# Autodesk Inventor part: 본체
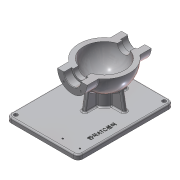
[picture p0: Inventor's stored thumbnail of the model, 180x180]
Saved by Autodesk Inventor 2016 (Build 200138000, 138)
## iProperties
Created: 2015-12
Part Number: 본체
Material: 알루미늄 6061
Document SubType Name: Modeling
Designer: mduedu
Density: 2.71 g/cm^3
Mass: 1388.35 g
Surface Area: 1121.73 cm^2
Volume: 512.305 cm^3
Appearance: 알루미늄 - 평지
Author: mduedu
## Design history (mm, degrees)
sketch "스케치1"
  geometry: L1 (-53, 0)-(53, 0); A1 r 53 centre (0, 0) between (53, 0) and (-53, 0); 2 further points
  constraints: 2 coincident, 2 end point, 2 point on circle, 1 centre point, 1 horizontal, 1 midpoint
  dimensions: "d0" = 53 radius of A1
revolve "회전1" sketch "스케치1" stored, may be unused: angle "d2" = 90 deg
feature "쉘1" dims "d11" = 10
node "작업 평면1"
sketch "스케치2"
  geometry: C1 r 31 at (0, 0); 1 further point
  constraints: 1 centre point, 1 coincident
  dimensions: "d4" = 62 diameter of C1
extrude "돌출1" join sketch "스케치2" stored distance "d5" = 10; taper "d6" = 0 deg
hole "구멍1" diameter "d14" = 35; stored, may be unused: countersink angle "d18" = 90 deg, drill point angle "d20" = 0 deg; dims "d12" = 10, "d13" = 10, "d15" = 6, "d16" = 4, "d17" = 2, "d19" = 16
hole "구멍2" diameter "d23" = 27; stored, may be unused: countersink angle "d27" = 90 deg, drill point angle "d29" = 0 deg; dims "d21" = 10, "d22" = 10, "d24" = 6, "d25" = 4, "d26" = 2, "d28" = 16
fillet "모깎기1" dims "d30" = 0.3
chamfer "모따기1" distance "d40" = 1; stored, may be unused: second distance "d41" = 2, angle "d42" = 45 deg
sketch "스케치4"
  geometry: L1 (0, 0)-(0, -25); L2 (0, 0)-(-17.678, -17.678); A1 r 25 centre (0, 0) between (-17.678, -17.678) and (0, -25); 1 further point
  constraints: 4 end point, 2 point on circle, 1 centre point, 1 coincident, 1 vertical
  dimensions: "d43" = 50 diameter of A1; "d47" = 45 deg angle of L1 L2
hole "구멍4" sketch "스케치4" at (-17.678, -17.678) diameter "d49" = 3.242; stored, may be unused: countersink angle "d53" = 90 deg, drill point angle "d55" = 118 deg; dims "d50" = 11, "d51" = 4, "d52" = 2, "d54" = 13
node "작업 평면3"
sketch "스케치6" dims "d22" = 10
  geometry: L1 (-70, -75)-(130, -75); L2 (130, -75)-(130, 75); L3 (130, 75)-(-70, 75); L4 (-70, 75)-(-70, -75); 2 further points
  constraints: 8 end point, 2 parallel, 1 coincident, 1 horizontal, 1 perpendicular
  dimensions: "d158" = 200 distance of L3.end L2.end; "d159" = 150 distance of L2.end L1.end; "d162" = 75 distance from line of L1 point (0, 0); "d163" = 70 distance from line of L4 point (0, 0)
extrude "돌출3" join sketch "스케치6" distance "d80" = 10; taper "d81" = 0 deg
sketch "스케치7"
  geometry: C1 r 20 at (0, 0); 2 further points
  constraints: 2 coincident, 1 centre point
  dimensions: "d82" = 40 diameter of C1
extrude "돌출4" join sketch "스케치7" stored distance "d84" = 10; taper "d85" = 0 deg
sketch "스케치8"
  geometry: 3 further points
  constraints: 2 coincident
hole "구멍6" sketch "스케치8" at (0, 0) diameter "d86" = 20; stored, may be unused: countersink angle "d90" = 90 deg, drill point angle "d92" = 118 deg; dims "d87" = 7, "d88" = 40, "d89" = 5, "d91" = 10
fillet "모깎기2" dims "d93" = 0.3
sketch "스케치9"
  geometry: L1 (-45, -75)-(-38.245, -36.692); L2 (70, -75)-(-130, -75) reference; A1 r 53 centre (0, 0) between (42.988, 31) and (42.988, -31) reference; 1 further point
  constraints: 2 end point, 1 coincident, 1 point on circle, 1 point on line
  dimensions: "d94" = 45 horizontal distance of L1.start point (0, 0); "d160" = 80 deg angle of L2 L1
feature "리브1" sketch "스케치9" dims "d96" = 1, "d97" = 8, "d98" = 0, "d99" = 0, "d100" = 1, "d101" = 1
fillet "모깎기3" dims "d120" = 3
fillet "모깎기4" dims "d121" = 3, "d122" = 3
fillet "모깎기5" dims "d123" = 3
sketch "스케치12"
  geometry: L1 (0, 100)-(0, -100); L2 (0, 100)-(100, 100); L3 (100, 100)-(100, -100); L4 (100, -100)-(0, -100); 2 further points
  constraints: 8 end point, 3 perpendicular, 1 coincident, 1 midpoint, 1 vertical
  dimensions: "d127" = 200 distance of L2.end L3.end; "d129" = 100 distance between parallel lines of L1 L3
extrude "돌출5" cut sketch "스케치12" stored distance "d130" = 10; taper "d131" = 0 deg
fillet "모깎기10" dims "d164" = 10
fillet "모깎기11" dims "d165" = 3
sketch "스케치15"
  geometry: C1 r 4 at (-120, 65); C2 r 4 at (60, 65); C3 r 4 at (60, -65); A1 r 10 centre (-120, 65) between (-120, 75) and (-130, 65) reference; A2 r 10 centre (60, 65) between (70, 65) and (60, 75) reference; A3 r 10 centre (60, -65) between (60, -75) and (70, -65) reference; 1 further point
  constraints: 3 centre point, 3 coincident, 2 equal radius
  dimensions: "d166" = 8 diameter of C1
extrude "돌출8" cut sketch "스케치15" stored distance "d167" = 10; taper "d168" = 0 deg
sketch "스케치16"
  geometry: L1 (-130, 65)-(-130, -65) reference; L2 (-120, -75)-(60, -75) reference; 2 further points
  constraints: 1 other
  dimensions: "d169" = 70 distance from line of point (-60, -55) L1; "d170" = 20 distance from line of point (-60, -55) L2
feature "엠보싱2" sketch "스케치16" dims "d171" = 0.5, "d172" = 0
sketch "스케치17"
  geometry: L1 (-120, 75)-(60, 75) reference; L2 (-130, -65)-(-130, 65) reference; 2 further points
  constraints: 1 vertical alignment
  dimensions: "d180" = 12 distance from line of L1 point (-114, 63); "d181" = 16 distance from line of point (-114, 63) L2; "d182" = 36 distance of point (-114, 27) point (-114, 63)
hole "구멍9" sketch "스케치17" at (-114, 63), (-114, 27) diameter "d173" = 3.242; stored, may be unused: countersink angle "d177" = 90 deg, drill point angle "d179" = 0 deg; dims "d174" = 6, "d175" = 4, "d176" = 2, "d178" = 8
node "솔리드1"
mirror "대칭1"
mirror "대칭2"
pattern_circular "원형 패턴1" dims angle "d57" = 360 deg
mirror "대칭3"
pattern_circular "원형 패턴3" dims angle "d103" = 360 deg
other parameters: "d3" = 67, "d77" = -85
